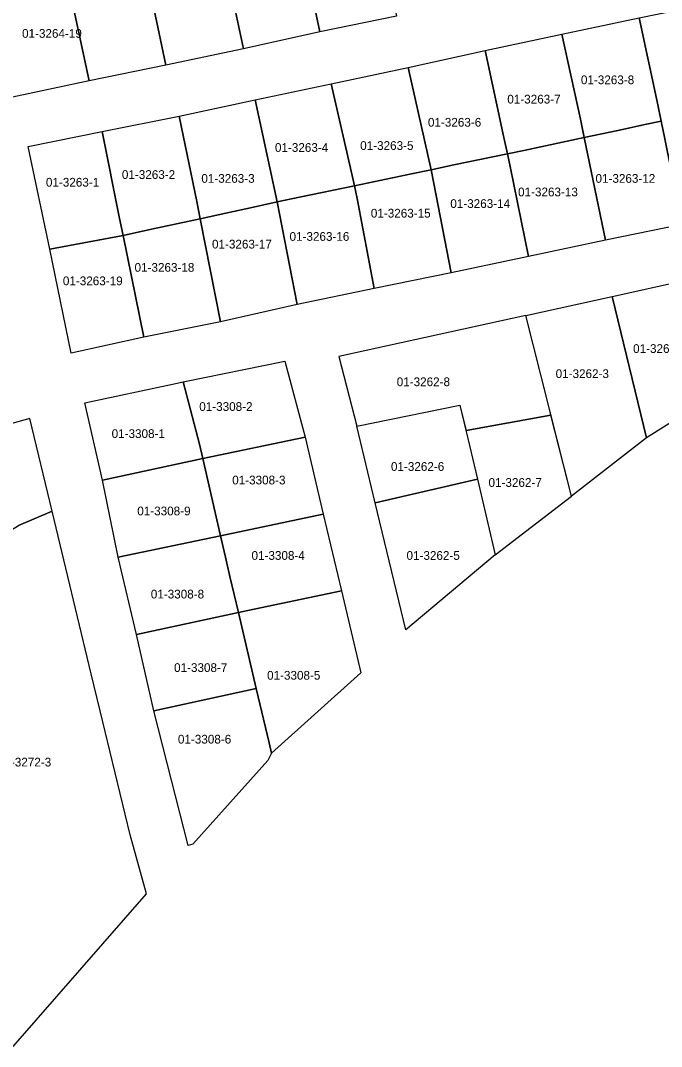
# Model space of a CAD drawing. Extents: x 419396 to 421519, y 4453567 to 4456767.
# Drawn here: x 420501 to 420574.3, y 4453711.7 to 4453829.1 of the extents above; entities that cross this region are included whole.
import ezdxf

# ---------------------------------------------------------------- set-up
doc = ezdxf.new("R2010")
doc.units = 0
doc.layers.add('0_KADASTRO', color=7, linetype='Continuous')

msp = doc.modelspace()

# ---------------------------------------------------------------- linework, layer by layer
at = {"layer": '0_KADASTRO'}
for p, q in [((420551.93, 4453782.18), (420561.64, 4453783.96)), ((420561.64, 4453783.96), (420551.93, 4453782.18)), ((420564, 4453774.67), (420561.64, 4453783.96)), ((420502.02, 4453783.56), (420486.47, 4453779.3)), ((420504.57, 4453772.95), (420502.02, 4453783.56)), ((420551.93, 4453782.18), (420551.95, 4453782.08)), ((420551.95, 4453782.08), (420553.23, 4453776.61))]:
    msp.add_line(p, q, dxfattribs=at)
for points in [[(420532.7, 4453839.62), (420536.67, 4453840.49), (420539.57, 4453841.13), (420541.5, 4453841.55), (420543.98, 4453829.58), (420535.22, 4453827.81), (420533.08, 4453837.86)], [(420523.96, 4453837.71), (420526.25, 4453838.22), (420529.75, 4453838.98), (420532.7, 4453839.62), (420533.08, 4453837.86), (420535.22, 4453827.81), (420526.48, 4453825.87), (420524.31, 4453836.05)], [(420515.1, 4453835.89), (420517.84, 4453836.45), (420522.44, 4453837.4), (420523.96, 4453837.71), (420524.31, 4453836.05), (420526.48, 4453825.87), (420517.57, 4453823.98), (420515.5, 4453833.96)], [(420506.25, 4453834.13), (420507.75, 4453834.42), (420515.1, 4453835.89), (420515.5, 4453833.96), (420517.57, 4453823.98), (420508.82, 4453822.21)], [(420497.37, 4453832.16), (420506.25, 4453834.13), (420508.82, 4453822.21), (420500.06, 4453820.34)], [(420571.75, 4453829.42), (420580.53, 4453831.2), (420582.56, 4453821.41), (420582.98, 4453819.42), (420583.4, 4453817.43), (420585.48, 4453807.67), (420576.67, 4453805.77), (420574.67, 4453815.57), (420574.26, 4453817.57), (420573.82, 4453819.64)], [(420562.9, 4453827.54), (420571.75, 4453829.42), (420573.82, 4453819.64), (420574.26, 4453817.57), (420572.58, 4453817.22), (420569.29, 4453816.51), (420565.46, 4453815.71), (420565.01, 4453817.81)], [(420554.1, 4453825.67), (420562.9, 4453827.54), (420565.01, 4453817.81), (420565.46, 4453815.71), (420558.53, 4453814.24), (420556.67, 4453813.85), (420556.27, 4453815.71)], [(420545.3, 4453823.72), (420554.1, 4453825.67), (420556.27, 4453815.71), (420556.67, 4453813.85), (420550.54, 4453812.57), (420547.93, 4453812.03)], [(420536.49, 4453821.85), (420545.3, 4453823.72), (420547.93, 4453812.03), (420545.68, 4453811.56), (420539.17, 4453810.2), (420538.72, 4453812.2)], [(420527.79, 4453820.01), (420536.49, 4453821.85), (420538.72, 4453812.2), (420539.17, 4453810.2), (420532.86, 4453808.88), (420530.32, 4453808.35)], [(420519.11, 4453818.17), (420527.79, 4453820.01), (420530.32, 4453808.35), (420527.61, 4453807.75), (420524.46, 4453807.05), (420521.53, 4453806.41), (420521.13, 4453808.37)], [(420510.29, 4453816.4), (420519.11, 4453818.17), (420521.13, 4453808.37), (420521.53, 4453806.41), (420520.26, 4453806.13), (420515.94, 4453805.21), (420512.7, 4453804.51), (420512.3, 4453806.46)], [(420565.46, 4453815.71), (420569.29, 4453816.51), (420572.58, 4453817.22), (420574.26, 4453817.57), (420574.67, 4453815.57), (420576.67, 4453805.77), (420567.88, 4453803.95)], [(420501.83, 4453814.67), (420510.29, 4453816.4), (420512.3, 4453806.46), (420512.7, 4453804.51), (420504.33, 4453802.92)], [(420556.67, 4453813.85), (420558.53, 4453814.24), (420565.46, 4453815.71), (420567.88, 4453803.95), (420559.07, 4453802.1), (420556.97, 4453812.38)], [(420547.93, 4453812.03), (420550.54, 4453812.57), (420556.67, 4453813.85), (420556.97, 4453812.38), (420559.07, 4453802.1), (420550.24, 4453800.22), (420548.23, 4453810.46)], [(420539.17, 4453810.2), (420545.68, 4453811.56), (420547.93, 4453812.03), (420548.23, 4453810.46), (420550.24, 4453800.22), (420541.43, 4453798.43), (420539.46, 4453808.73)], [(420530.32, 4453808.35), (420532.86, 4453808.88), (420539.17, 4453810.2), (420539.46, 4453808.73), (420541.43, 4453798.43), (420532.62, 4453796.61)], [(420521.53, 4453806.41), (420524.46, 4453807.05), (420527.61, 4453807.75), (420530.32, 4453808.35), (420532.62, 4453796.61), (420523.84, 4453794.63)], [(420512.7, 4453804.51), (420515.94, 4453805.21), (420520.26, 4453806.13), (420521.53, 4453806.41), (420523.84, 4453794.63), (420515.07, 4453792.85)], [(420504.33, 4453802.92), (420512.7, 4453804.51), (420515.07, 4453792.85), (420506.76, 4453791.05)], [(420568.66, 4453797.53), (420577.41, 4453799.45), (420579.93, 4453789.27), (420580.54, 4453786.8), (420580.64, 4453786.41), (420572.59, 4453781.35)], [(420558.76, 4453795.34), (420568.66, 4453797.53), (420572.59, 4453781.35), (420564, 4453774.67), (420561.55, 4453784.33), (420560.48, 4453788.54)], [(420519.57, 4453787.75), (420531.19, 4453790.12), (420533.54, 4453781.42), (420521.81, 4453778.98), (420521.42, 4453780.61)], [(420508.31, 4453785.35), (420518.36, 4453787.49), (420519.57, 4453787.75), (420521.42, 4453780.61), (420521.81, 4453778.98), (420510.35, 4453776.51)], [(420539.44, 4453782.68), (420551.23, 4453785.1), (420551.95, 4453782.08), (420553.23, 4453776.61), (420541.52, 4453773.92)], [(420521.81, 4453778.98), (420533.54, 4453781.42), (420535.6, 4453772.61), (420523.84, 4453770.14)], [(420510.35, 4453776.51), (420521.81, 4453778.98), (420523.84, 4453770.14), (420512.15, 4453767.69)], [(420541.52, 4453773.92), (420553.23, 4453776.61), (420555.26, 4453767.97), (420545.03, 4453759.38)], [(420523.84, 4453770.14), (420535.6, 4453772.61), (420537.69, 4453763.85), (420526.98, 4453761.61), (420525.89, 4453761.38), (420524.92, 4453765.5), (420524.57, 4453767.02), (420524.41, 4453767.71)], [(420512.15, 4453767.69), (420523.84, 4453770.14), (420524.41, 4453767.71), (420524.57, 4453767.02), (420524.92, 4453765.5), (420525.89, 4453761.38), (420514.23, 4453758.86)], [(420525.89, 4453761.38), (420526.98, 4453761.61), (420537.69, 4453763.85), (420539.9, 4453754.47), (420529.66, 4453745.29), (420529.39, 4453746.47), (420527.93, 4453752.68)], [(420514.23, 4453758.86), (420525.89, 4453761.38), (420527.93, 4453752.68), (420516.21, 4453750.1)], [(420516.21, 4453750.1), (420527.93, 4453752.68), (420529.39, 4453746.47), (420529.66, 4453745.29), (420529.27, 4453744.45), (420520.69, 4453734.86), (420520.14, 4453734.72), (420517.74, 4453744.11)]]:
    msp.add_lwpolyline(points, close=True, dxfattribs=at)
for points in [[(420558.76, 4453795.34), (420537.36, 4453790.65), (420539.44, 4453782.68), (420551.23, 4453785.1)], [(420561.64, 4453783.96), (420561.55, 4453784.33), (420560.48, 4453788.54), (420558.76, 4453795.34)], [(420551.23, 4453785.1), (420551.93, 4453782.18), (420551.93, 4453782.18)], [(420553.23, 4453776.61), (420555.26, 4453767.97), (420564, 4453774.67)], [(420496.56, 4453768.75), (420500.73, 4453771.31), (420504.57, 4453772.95)], [(420500.12, 4453711.71), (420515.37, 4453729.16), (420513.5, 4453735.91), (420510.08, 4453750.1), (420509.06, 4453754.35), (420504.57, 4453772.95), (420500.73, 4453771.31)]]:
    msp.add_lwpolyline(points, dxfattribs=at)

# ---------------------------------------------------------------- texts
for s, p in [('01-3264-19', (420501.14, 4453827.12)), ('01-3263-8', (420565.07, 4453821.81)), ('01-3263-7', (420556.65, 4453819.6)), ('01-3263-6', (420547.57, 4453816.95)), ('01-3263-4', (420530.07, 4453814.07)), ('01-3263-5', (420539.82, 4453814.29)), ('01-3263-2', (420512.56, 4453810.97)), ('01-3263-1', (420503.87, 4453810.09)), ('01-3263-3', (420521.65, 4453810.53)), ('01-3263-12', (420566.74, 4453810.53)), ('01-3263-13', (420557.88, 4453808.98)), ('01-3263-14', (420550.13, 4453807.65)), ('01-3263-15', (420541.04, 4453806.55)), ('01-3263-16', (420531.74, 4453803.89)), ('01-3263-17', (420522.87, 4453803.01)), ('01-3263-18', (420514.01, 4453800.35)), ('01-3263-19', (420505.81, 4453798.81)), ('01-3262-2', (420571.04, 4453791.06)), ('01-3262-3', (420562.18, 4453788.19)), ('01-3262-8', (420544, 4453787.26)), ('01-3308-2', (420521.41, 4453784.43)), ('01-3308-1', (420511.39, 4453781.33)), ('01-3262-6', (420543.34, 4453777.57)), ('01-3308-3', (420525.18, 4453776.02)), ('01-3262-7', (420554.5, 4453775.74)), ('01-3308-9', (420514.32, 4453772.48)), ('01-3308-4', (420527.39, 4453767.39)), ('01-3262-5', (420545.12, 4453767.39)), ('01-3308-8', (420515.87, 4453762.97)), ('01-3308-7', (420518.53, 4453754.56)), ('01-3308-5', (420529.17, 4453753.68)), ('01-3308-6', (420518.97, 4453746.37)), ('01-3272-3', (420498.38, 4453743.75))]:
    msp.add_text(s, height=1, dxfattribs=at).set_placement(p)

doc.saveas('drawing.dxf')
